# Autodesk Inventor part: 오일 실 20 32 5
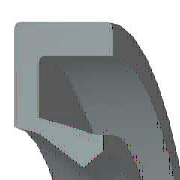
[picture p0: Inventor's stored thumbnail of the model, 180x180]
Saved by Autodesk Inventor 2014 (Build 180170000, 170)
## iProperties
IsCustomPart: 0
Created: 2012-02
Part Number: 오일 실 20 32 5
Material: 고무
Description: 오일 실 - 비스프링, 조립 GA
Document SubType Name: Modeling
Standard: JIS B 2402
Designer: mduedu
Standards Organization: JIS
Language: ko-KR
Size Designation: 20 32 5 A
Categories: <MemberInstance><Categories><Category DisplayName="샤프트 부품" InternalName="7f7aeb1f-a693-4053-b835-cee3144e0d98" Mnemonic="SHFT"><Category DisplayName="실링" Intern
Density: 0.93 g/cm^3
Appearance: Rubber-Black
Author: mduedu
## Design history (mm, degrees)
fillet "모깎기2" dims "d33" = 0.5
body "Solid1"
revolve "회전1" stored, may be unused: angle "d27" = 360 deg
fillet "모깎기1" dims "d28" = 0.25 (= 0.05 x b)
sketch "스케치2"
  geometry: L1 (11.971, -3.75)-(12.571, -5); L2 (11.171, -3.438)-(11.971, -3.75); L3 (10, -1.375)-(11.171, -3.438); L4 (10.923, -0.75)-(10, -1.375); L5 (13.6, -4.375)-(10.923, -0.75); L6 (13.6, -0.25)-(13.6, -4.375); L7 (14.8, -0.25)-(13.6, -0.25); L8 (14.8, 0)-(14.8, -0.25); L9 (16, 0)-(14.8, 0); L10 (16, -5)-(16, 0); L11 (12.571, -5)-(16, -5); L12 (0, -9.6)-(0, 1.6) reference; L13 (28, 0)-(14, 0) reference
  constraints: 22 end point, 3 horizontal, 3 vertical
  dimensions: "d2" = 5 distance of L10.start L9.start (= b); "d4" = 1.2 distance of L9.start L8.start (= 0.1 x dd - 0.1 x Diam); "d6" = 0.25 distance of L8.start L7.start (= 0.05 x b); "d8" = 0.92308 horizontal distance of L4.start L3.start (= 0.0769231 x dd - 0.0769231 x Diam); "d10" = 0.625 vertical distance of L5.start L10.start (= 0.125 x b); "d12" = 1.2 distance of L7.start L6.start (= 0.1 x dd - 0.1 x Diam); "d14" = 0.5 vertical distance of L4.start L6.start (= 0.1 x b); "d16" = 3.42857 distance of L1.end L10.start (= 0.285714 x dd - 0.285714 x Diam); "d18" = 0.6 horizontal distance of L1.start L1.end (= 0.05 x dd - 0.05 x Diam); "d20" = 0.625 vertical distance of L4.start L3.start (= 0.125 x b); "d22" = 1.25 vertical distance of L1.start L1.end (= 0.25 x b); "d24" = 0.8 horizontal distance of L2.start L1.start (= 0.0666667 x dd - 0.0666667 x Diam); "d26" = 0.3125 vertical distance of L2.start L1.start (= 0.0625 x b); "d29" = 0 distance between parallel lines of L13 L9; "d30" = 10 distance from line of L3.start L12 (= 0.5 x Diam); "d31" = 16 distance between parallel lines of L12 L10 (= 0.5 x dd)
other parameters: "dd" = 32 [user parameter; used in 7 equation terms], "b" = 5 [user parameter; used in 8 equation terms], "d1" = 8 (derived), "d3" = 2 (derived), "d5" = 0.4 (derived), "d7" = 1.53846 (derived), "d9" = 1 (derived), "d11" = 2 (derived), "d13" = 0.8 (derived), "d15" = 5.71429 (derived), "d17" = 1 (derived), "d19" = 1 (derived), "d21" = 2 (derived), "d23" = 1.33333 (derived), "d25" = 0.5 (derived), "d32" = 0
